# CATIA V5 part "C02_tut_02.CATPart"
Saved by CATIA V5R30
Part number: Part1
Bounding box of the stored display mesh (mm): x 0 to 0, y -60 to 60, z -50 to 50
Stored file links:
  D:\PROJECTS\CATIA V56R 2020\Resources\c02_catia_v5_6r2020_tut\C02_tut_02.CATPart
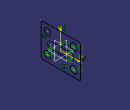
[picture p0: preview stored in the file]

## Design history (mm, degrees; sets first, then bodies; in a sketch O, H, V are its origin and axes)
Body1 (main body)
  Sketch1 on yz-plane, origin (0, 0, 0), H (0, 1, 0), V (0, 0, 1)
    line L1 (-60, -50) -> (60, -50)
    line L2 (60, -50) -> (60, 50)
    line L3 (60, 50) -> (-60, 50)
    line L4 (-60, 50) -> (-60, -50)
    line L5 (-30, 10) -> (30, 10)
    arc A1 centre (30, 0) radius 10 from (30, 10) to (30, -10) cw
    line L6 (30, -10) -> (-30, -10)
    arc A2 centre (-30, 0) radius 10 from (-30, -10) to (-30, 10) cw
    circle A3 centre (40, -30) radius 10
    circle A4 centre (40, 30) radius 10
    circle A5 centre (-40, 30) radius 10
    circle A6 centre (-40, -30) radius 10
    radius A3 = 10
    radius A4 = 10
    radius A6 = 10
    horizontal: L1 H, L3 H, L5 H
    vertical: L2 V, L4 V
    tangency: A1 L5, L6 A1, A2 L6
